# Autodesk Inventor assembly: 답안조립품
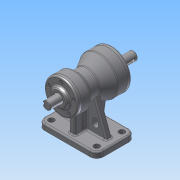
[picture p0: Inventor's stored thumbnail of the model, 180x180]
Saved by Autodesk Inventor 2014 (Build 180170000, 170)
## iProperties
Created: 2015-08
Part Number: 답안조립품
Document SubType Name: Weldment
Designer: SDA24
Weld Material: Welded Aluminum-6061
Author: SDA24
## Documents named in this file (10)
- C:\Users\SDA24\Desktop\450805V1011\답안조립품.iam
- C:\Users\SDA24\Desktop\450805V1011\본체.ipt
- C:\Users\SDA24\Desktop\450805V1011\축.ipt
- C:\Users\SDA24\Desktop\450805V1011\베어링 6203.ipt
- C:\Users\SDA24\Desktop\450805V1011\베어링 6205.ipt
- C:\Users\SDA24\Desktop\450805V1011\뒤커버.ipt
- C:\Users\SDA24\Desktop\450805V1011\앞커버.ipt
- C:\Users\SDA24\Desktop\450805V1011\오일실 .ipt
- 오일실 .ipt
- C:\Users\SDA24\Desktop\450805V1011\M4x0.5.ipt
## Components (10 placed, 1 different names)
1. M4x0.5:1
2. M4x0.5:2
3. M4x0.5:3
4. M4x0.5:4
5. M4x0.5:5
6. M4x0.5:6
7. M4x0.5:7
8. M4x0.5:8
9. M4x0.5:9
10. M4x0.5:10
